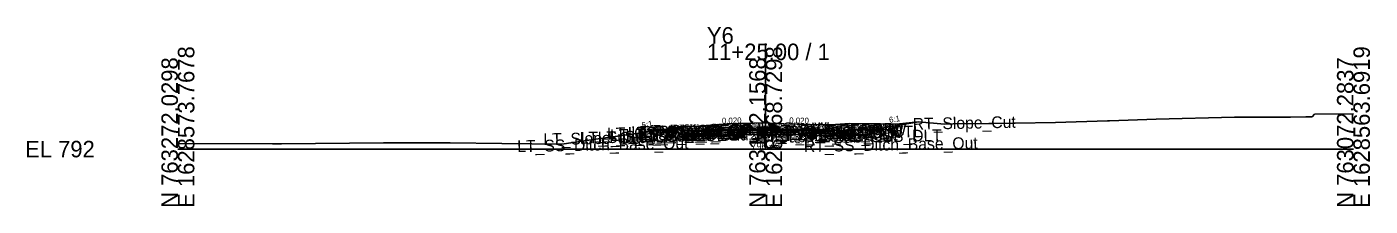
# Model space of a CAD drawing. Extents: x -26 to 203, y -10 to 6017.
# Drawn here: x -25.7 to 202.8, y 2490.3 to 2520.8 of the extents above; entities that cross this region are included whole.
import ezdxf

# ---------------------------------------------------------------- set-up
doc = ezdxf.new("R2010")
doc.units = 0
for name, color, linetype in [('Default', 7, 'Continuous'), ('Exist Cross Section Cell', 7, 'Continuous'), ('Exist XS Center Line Elevation Label', 7, 'Continuous'), ('Exist XS Ground Line', 7, 'Continuous'), ('Prop CMT Concrete Structures', 7, 'Continuous'), ('Prop CMT Pvmt Course 1', 7, 'Continuous'), ('Prop CMT Pvmt Course 2', 7, 'Continuous'), ('Prop CMT Pvmt Course 3', 7, 'Continuous'), ('Prop CMT Pvmt Surface', 7, 'Continuous'), ('Prop CMT Pvmt Surface Shoulder', 7, 'Continuous'), ('Prop CMT Pvmt Wedge Surface 2', 7, 'Continuous'), ('Prop CMT Pvmt Wedge Surface 3', 7, 'Continuous'), ('Prop CMT Shld Paved Course 1', 7, 'Continuous'), ('Prop CMT Shld Paved Course 2', 7, 'Continuous'), ('Prop CMT Shld Paved Course 3', 7, 'Continuous'), ('Prop CMT Slope Grass', 7, 'Continuous'), ('Prop CMT Subgrade Earthwork', 7, 'Continuous'), ('Prop XS SE Text', 7, 'Continuous'), ('Prop XS Side Slope Text', 7, 'Continuous'), ('Scratch_Level_0', 7, 'Continuous')]:
    doc.layers.add(name, color=color, linetype=linetype)

msp = doc.modelspace()

# ---------------------------------------------------------------- linework, layer by layer
at = {"layer": 'Exist Cross Section Cell'}
for p, q in [((100, 2500), (100, 2517.93)), ((0, 2500), (100, 2500)), ((100, 2500), (200, 2500))]:
    msp.add_line(p, q, dxfattribs=at)
at = {"layer": 'Exist XS Ground Line'}
msp.add_lwpolyline([(0, 2500.94), (16.12, 2500.87), (17.63, 2500.88), (34.98, 2501.09), (39.1, 2501.09), (46.34, 2501.07), (55.09, 2500.94), (65.31, 2500.84), (70.7, 2501.63), (86.99, 2503.9), (88.15, 2503.86), (89.15, 2503.98), (93.56, 2504.3), (100.28, 2504.49), (100.83, 2504.34), (109.82, 2504.13), (111.08, 2504.11), (114.25, 2504.33), (119.54, 2504.27), (122.28, 2504.21), (126, 2504.61), (130.44, 2504.25), (131.91, 2504.27), (137.97, 2504.35), (138.51, 2504.37), (142.13, 2504.41), (142.46, 2504.41), (149.29, 2504.5), (158.18, 2504.83), (158.49, 2504.83), (166.46, 2505.06), (179.78, 2505.4), (180.88, 2505.4), (189.29, 2505.43), (191.89, 2505.5), (192.97, 2505.46), (193.39, 2505.96), (200, 2505.98)], dxfattribs=at)
at = {"layer": 'Prop CMT Concrete Structures'}
for points in [[(86.65, 2503.24), (86.65, 2502.66), (88.65, 2502.66)], [(88.65, 2503.24), (87.65, 2503.16), (86.65, 2503.24)], [(88.65, 2502.66), (88.65, 2503.24)], [(111.45, 2502.65), (111.45, 2503.24)], [(113.45, 2503.24), (113.45, 2502.65), (111.45, 2502.65)], [(111.45, 2503.24), (112.45, 2503.15), (113.45, 2503.24)]]:
    msp.add_lwpolyline(points, dxfattribs=at)
at = {"layer": 'Prop CMT Pvmt Course 1'}
for points in [[(100.01, 2503.47), (88.65, 2503.24)], [(88.65, 2503.24), (88.65, 2502.99)], [(88.65, 2502.99), (100.01, 2503.22)], [(100.01, 2503.47), (89.15, 2503.25)], [(100.01, 2503.34), (100.01, 2503.47)], [(100.01, 2503.22), (100.01, 2503.47)], [(100.01, 2503.47), (110.91, 2503.25)], [(100.01, 2503.34), (100.01, 2503.47)], [(100.01, 2503.47), (111.45, 2503.24)], [(100.01, 2503.22), (100.01, 2503.47)], [(111.45, 2502.99), (100.01, 2503.22)], [(111.45, 2503.24), (111.45, 2502.99)]]:
    msp.add_lwpolyline(points, dxfattribs=at)
at = {"layer": 'Prop CMT Pvmt Course 2'}
for points in [[(100.01, 2503.22), (88.65, 2502.99)], [(88.65, 2502.99), (88.65, 2502.66)], [(88.65, 2502.66), (100.01, 2502.88)], [(100.01, 2502.88), (100.01, 2503.22)], [(100.01, 2502.88), (100.01, 2503.22)], [(100.01, 2503.22), (111.45, 2502.99)], [(111.45, 2502.65), (100.01, 2502.88)], [(111.45, 2502.99), (111.45, 2502.65)]]:
    msp.add_lwpolyline(points, dxfattribs=at)
at = {"layer": 'Prop CMT Pvmt Course 3'}
msp.add_line((113.45, 2502.65), (113.95, 2502.65), dxfattribs=at)
for points in [[(100.01, 2502.88), (88.65, 2502.66)], [(88.65, 2502.66), (88.65, 2502.32)], [(88.65, 2502.32), (100.01, 2502.55)], [(100.01, 2502.55), (100.01, 2502.88)], [(100.01, 2502.88), (111.45, 2502.65)], [(100.01, 2502.55), (100.01, 2502.88)], [(111.45, 2502.32), (100.01, 2502.55)], [(111.45, 2502.65), (111.45, 2502.32)]]:
    msp.add_lwpolyline(points, dxfattribs=at)
at = {"layer": 'Prop CMT Pvmt Surface'}
for points in [[(100.01, 2503.47), (88.65, 2503.24)], [(100.01, 2503.47), (89.15, 2503.25)], [(100.01, 2503.47), (111.45, 2503.24)], [(100.01, 2503.47), (110.91, 2503.25)]]:
    msp.add_lwpolyline(points, dxfattribs=at)
at = {"layer": 'Prop CMT Pvmt Surface Shoulder'}
for points in [[(88.65, 2503.24), (88.65, 2503.24)], [(111.45, 2503.24), (111.45, 2503.24)]]:
    msp.add_lwpolyline(points, dxfattribs=at)
at = {"layer": 'Prop CMT Pvmt Wedge Surface 2'}
for points in [[(100.01, 2503.22), (89.15, 2503)], [(100.01, 2503.22), (100.01, 2503.47)], [(100.01, 2503.22), (100.01, 2503.47)], [(100.01, 2503.22), (100.01, 2503.47)], [(100.01, 2503.22), (100.01, 2503.47)], [(100.01, 2503.22), (110.91, 2503)]]:
    msp.add_lwpolyline(points, dxfattribs=at)
at = {"layer": 'Prop CMT Pvmt Wedge Surface 3'}
for points in [[(100.01, 2502.88), (89.15, 2502.67)], [(100.01, 2502.88), (100.01, 2503.47)], [(100.01, 2502.88), (100.01, 2503.47)], [(100.01, 2502.88), (100.01, 2503.47)], [(100.01, 2502.88), (100.01, 2503.47)], [(100.01, 2502.88), (110.91, 2502.67)]]:
    msp.add_lwpolyline(points, dxfattribs=at)
at = {"layer": 'Prop CMT Shld Paved Course 1'}
for points in [[(88.65, 2503.24), (88.65, 2503.24)], [(88.65, 2502.99), (88.65, 2503.24)], [(111.45, 2503.24), (111.45, 2503.24)], [(111.45, 2502.99), (111.45, 2503.24)]]:
    msp.add_lwpolyline(points, dxfattribs=at)
at = {"layer": 'Prop CMT Shld Paved Course 2'}
for p, q in [((86.65, 2502.66), (88.65, 2502.66)), ((113.45, 2502.65), (111.45, 2502.65))]:
    msp.add_line(p, q, dxfattribs=at)
for points in [[(88.65, 2502.66), (88.65, 2502.99)], [(111.45, 2502.65), (111.45, 2502.99)]]:
    msp.add_lwpolyline(points, dxfattribs=at)
at = {"layer": 'Prop CMT Shld Paved Course 3'}
for p, q in [((85.81, 2502.32), (88.65, 2502.32)), ((114.29, 2502.31), (111.45, 2502.32))]:
    msp.add_line(p, q, dxfattribs=at)
for points in [[(88.65, 2502.66), (86.65, 2502.66), (86.15, 2502.66), (85.81, 2502.32)], [(88.65, 2502.32), (88.65, 2502.66)], [(111.45, 2502.32), (111.45, 2502.65)], [(111.45, 2502.65), (113.95, 2502.65), (113.95, 2502.65), (114.29, 2502.31)]]:
    msp.add_lwpolyline(points, dxfattribs=at)
at = {"layer": 'Prop CMT Slope Grass'}
for points in [[(86.65, 2503.24), (81.65, 2503.34), (78.57, 2502.72)], [(113.45, 2503.24), (118.45, 2503.34), (126, 2504.61)]]:
    msp.add_lwpolyline(points, dxfattribs=at)
at = {"layer": 'Prop CMT Subgrade Earthwork'}
for p, q in [((85.81, 2502.32), (84.85, 2503.28)), ((114.29, 2502.31), (115.25, 2503.27)), ((88.65, 2502.32), (85.81, 2502.32)), ((111.45, 2502.32), (114.29, 2502.31))]:
    msp.add_line(p, q, dxfattribs=at)
for points in [[(100.01, 2502.55), (88.65, 2502.32)], [(100.01, 2502.55), (111.45, 2502.32)]]:
    msp.add_lwpolyline(points, dxfattribs=at)

# ---------------------------------------------------------------- texts
at = {"layer": 'Default'}
msp.add_text('-', height=0.0001, dxfattribs=at).set_placement((0, 2500))
at = {"layer": 'Exist Cross Section Cell'}
for s, p in [('Y6', (90, 2517.93)), ('11+25.00 / 1', (90, 2515.13)), ('EL 792', (-26, 2498.6))]:
    msp.add_text(s, height=2.8, dxfattribs=at).set_placement(p)
for s, p in [('E 1628573.7678', (2.8, 2490)), ('E 1628568.7298', (102.8, 2490)), ('E 1628563.6919', (202.8, 2490)), ('N 763272.0298', (0, 2490)), ('N 763172.1568', (100, 2490)), ('N 763072.2837', (200, 2490))]:
    msp.add_text(s, height=2.8, rotation=90, dxfattribs=at).set_placement(p)
at = {"layer": 'Exist XS Center Line Elevation Label'}
msp.add_text('796.49', height=1.2, dxfattribs=at).set_placement((97.53, 2499.89))
at = {"layer": 'Prop XS SE Text'}
for rotation, p in [(1.1456, (92.56, 2504.32)), (358.854, (104, 2504.39))]:
    msp.add_text('0.020', height=1, rotation=rotation, dxfattribs=at).set_placement(p)
at = {"layer": 'Prop XS Side Slope Text'}
for s, rotation, p in [('5:1', 11.3099, (79.02, 2503.52)), ('6:1', 9.5865, (121.08, 2504.45))]:
    msp.add_text(s, height=1, rotation=rotation, dxfattribs=at).set_placement(p)
at = {"layer": 'Scratch_Level_0'}
for s, p in [('RT_Slope_Cut', (125.03, 2503.28)), ('LT_Slope_Cut', (62.2, 2500.67)), ('LT_Sub_OSS_DLT', (68.39, 2500.92)), ('LT_Sub_Trench_Out', (71.44, 2500.98)), ('LT_GS_OS_CTL', (73.04, 2501.63)), ('LT_PS3_Shelf_Out', (73.56, 2501.35)), ('LT_PV2_OEEOP_W', (76.59, 2501.75)), ('LT_PV3_OEEOP_W', (76.59, 2501.41)), ('LT_PV1_OEEOP_W', (77.16, 2501.88)), ('LT_PS3_OEOP', (78.31, 2501.45)), ('LT_PS2_OEOP', (78.65, 2501.79)), ('LT_Sub_OEOT', (78.75, 2501.12)), ('LT_PV2_OEOT', (78.85, 2501.79)), ('LT_PV3_OEOT', (78.85, 2501.46)), ('LT_PV1_OEEOP', (79.05, 2502.05)), ('LT_PV1_OEOT', (79.41, 2502.05)), ('LT_PS1_OEOP', (79.48, 2502.06)), ('RT_PV1_PGL_W', (89.88, 2502.14)), ('LT_PV1_PGL_W', (89.92, 2502.14)), ('Sub_PGL', (93.84, 2501.43)), ('PV2_PGL', (93.94, 2502.09)), ('PV3_PGL', (93.94, 2501.76)), ('PV1_PGL', (94.51, 2502.36)), ('RT_Sub_Trench_Out', (97.07, 2500.98)), ('RT_PV2_OEEOP_W', (98.3, 2501.75)), ('RT_PV3_OEEOP_W', (98.3, 2501.41)), ('RT_PS3_Shelf_Out', (98.51, 2501.35)), ('RT_PV1_OEEOP_W', (98.87, 2501.88)), ('RT_PV1_OEEOP', (100.76, 2502.05)), ('RT_Sub_OEOT', (101.5, 2501.12)), ('RT_PV2_OEOT', (101.6, 2501.79)), ('RT_PV3_OEOT', (101.6, 2501.46)), ('RT_PS2_OEOP', (101.92, 2501.79)), ('RT_PV1_OEOT', (102.17, 2502.05)), ('RT_PS1_OEOP', (102.23, 2502.05)), ('RT_PS3_OEOP', (102.26, 2501.45)), ('RT_GS_OS_CTL', (105.8, 2501.62)), ('RT_Sub_OSS_DLT', (106.51, 2500.91)), ('LT_SS_Ditch_Base_Out', (57.75, 2499.48)), ('RT_SS_Ditch_Base_Out', (106.51, 2499.48))]:
    msp.add_text(s, height=2, rotation=1.1458, dxfattribs=at).set_placement(p)

doc.saveas('drawing.dxf')
